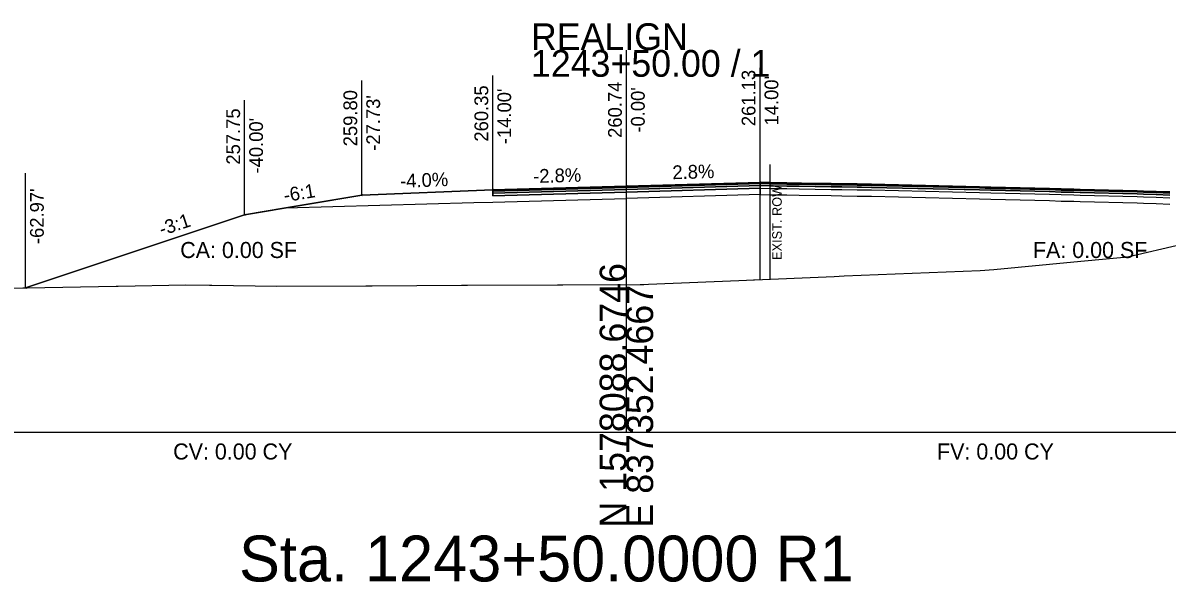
# Model space of a CAD drawing. Extents: x -26 to 6303, y -16 to 9563.
# Drawn here: x 2086.8 to 2206.7, y 4484.3 to 4542.8 of the extents above; entities that cross this region are included whole.
import ezdxf

# ---------------------------------------------------------------- set-up
doc = ezdxf.new("R2010")
doc.units = 0
for name, color, linetype in [('ASPHALT_19MM1', 7, 'Continuous'), ('ASPHALT_9_5MM1', 7, 'Continuous'), ('CONST_DCH', 7, 'Continuous'), ('CONST_LV3', 7, 'Continuous'), ('Default', 7, 'Continuous'), ('Draft_XS_Text', 7, 'Continuous'), ('DTM_P_FINISHED_GRADE', 7, 'Continuous'), ('DTM_P_FINISHED_GRADE2', 7, 'Continuous'), ('DTM_TEMP_DROP', 7, 'Continuous'), ('DTM_X_GROUND', 7, 'Continuous'), ('TRANS_EOP_PAVED', 7, 'Continuous'), ('TRANS_PAVED_SHOULDERS', 7, 'Continuous'), ('XS_CELL', 7, 'Continuous'), ('XS_M_SHAPES_EARTHWORK', 7, 'Continuous'), ('XS_P_ASPHALT', 7, 'Continuous'), ('XS_P_GROUND', 7, 'Continuous'), ('XS_P_SHOULDER', 7, 'Continuous'), ('XS_P_SUBGRADE_GRANULAR', 7, 'Continuous'), ('XS_P_TX_CLEARZONE', 7, 'Continuous'), ('XS_P_TX_FS_BS', 7, 'Continuous'), ('XS_SHEET_EW_TX_AREA', 7, 'Continuous'), ('XS_SHEET_EW_TX_VOLUME', 7, 'Continuous'), ('XS_X_ROW', 7, 'Continuous')]:
    doc.layers.add(name, color=color, linetype=linetype)

msp = doc.modelspace()

# ---------------------------------------------------------------- linework, layer by layer
at = {"layer": 'ASPHALT_19MM1'}
for points in [[(2136, 4525.01), (2136, 4524.74), (2150, 4525.13), (2150, 4525.13), (2164, 4525.53), (2164, 4525.53), (2164, 4525.8), (2164, 4525.8), (2164, 4525.8), (2150, 4525.41), (2150, 4525.41), (2136, 4525.01), (2136, 4525.01)], [(2164, 4525.8), (2164, 4525.53), (2164.98, 4525.51), (2165.2, 4525.51), (2166.82, 4525.49), (2168.12, 4525.47), (2171.44, 4525.41), (2172.57, 4525.4), (2174.17, 4525.37), (2174.62, 4525.36), (2175.69, 4525.35), (2186.99, 4525.08), (2188.17, 4525.03), (2194.33, 4524.91), (2195.56, 4524.86), (2196.9, 4524.83), (2197.54, 4524.8), (2203.52, 4524.66), (2204.19, 4524.63), (2205.52, 4524.6), (2206.93, 4524.53)], [(2206.93, 4524.8), (2205.52, 4524.87), (2204.19, 4524.9), (2203.52, 4524.93), (2197.54, 4525.07), (2196.9, 4525.1), (2195.56, 4525.13), (2194.33, 4525.18), (2188.17, 4525.31), (2186.99, 4525.35), (2175.69, 4525.62), (2174.62, 4525.64), (2174.17, 4525.64), (2172.57, 4525.67), (2171.44, 4525.68), (2168.12, 4525.74), (2166.82, 4525.76), (2165.2, 4525.78), (2164.98, 4525.78), (2164, 4525.8)]]:
    msp.add_lwpolyline(points, dxfattribs=at)
at = {"layer": 'ASPHALT_9_5MM1'}
for points in [[(2136, 4525.35), (2136, 4525.22), (2150, 4525.61), (2150, 4525.61), (2164, 4526.01), (2164, 4526.01), (2164, 4526.13), (2164, 4526.13), (2164, 4526.13), (2150, 4525.74), (2150, 4525.74), (2136, 4525.35), (2136, 4525.35)], [(2164, 4526.13), (2164, 4526.01), (2164.98, 4525.99), (2165.2, 4525.99), (2166.82, 4525.97), (2168.12, 4525.95), (2171.44, 4525.89), (2172.57, 4525.88), (2174.17, 4525.85), (2174.62, 4525.84), (2175.69, 4525.83), (2186.99, 4525.56), (2188.17, 4525.51), (2194.33, 4525.39), (2195.56, 4525.33), (2196.9, 4525.31), (2197.54, 4525.28), (2203.52, 4525.14), (2204.19, 4525.11), (2205.52, 4525.08), (2206.93, 4525.01)], [(2206.93, 4525.14), (2205.52, 4525.2), (2204.19, 4525.23), (2203.52, 4525.26), (2197.54, 4525.4), (2196.9, 4525.43), (2195.56, 4525.46), (2194.33, 4525.51), (2188.17, 4525.64), (2186.99, 4525.69), (2175.69, 4525.95), (2174.62, 4525.97), (2174.17, 4525.98), (2172.57, 4526), (2171.44, 4526.02), (2168.12, 4526.07), (2166.82, 4526.09), (2165.2, 4526.11), (2164.98, 4526.12), (2164, 4526.13)]]:
    msp.add_lwpolyline(points, dxfattribs=at)
at = {"layer": 'CONST_LV3'}
for points in [[(2172.7, 4526), (2164, 4526.13), (2164, 4526.13), (2164, 4526.13), (2150, 4525.74)], [(2164, 4526.13), (2164, 4524.86), (2164.98, 4524.85), (2165.2, 4524.84), (2166.82, 4524.82), (2168.12, 4524.8), (2171.44, 4524.75), (2172.57, 4524.73), (2174.17, 4524.7), (2174.62, 4524.7), (2175.69, 4524.68), (2186.99, 4524.41), (2188.17, 4524.37), (2194.33, 4524.24), (2195.56, 4524.19), (2196.9, 4524.16), (2197.54, 4524.13), (2203.52, 4523.99), (2204.19, 4523.96), (2205.52, 4523.93), (2206.93, 4523.87)], [(2206.93, 4525.14), (2205.52, 4525.2), (2204.19, 4525.23), (2203.52, 4525.26), (2197.54, 4525.4), (2196.9, 4525.43), (2195.56, 4525.46), (2194.33, 4525.51), (2188.17, 4525.64), (2186.99, 4525.69), (2175.69, 4525.95), (2174.62, 4525.97), (2174.17, 4525.97), (2172.57, 4526), (2171.44, 4526.02), (2168.12, 4526.07), (2166.82, 4526.09), (2165.2, 4526.11), (2164.98, 4526.12), (2164, 4526.13)], [(2114.3, 4523.47), (2110, 4522.75)]]:
    msp.add_lwpolyline(points, dxfattribs=at)
at = {"layer": 'Default'}
msp.add_lwpolyline([(2172.7, 4526), (2174.04, 4525.98), (2174.44, 4525.97), (2175.02, 4525.96), (2175.72, 4525.95), (2175.81, 4525.95), (2177.77, 4525.91), (2184.5, 4525.76), (2193.53, 4525.53), (2194.68, 4525.48), (2196.83, 4525.43), (2196.83, 4525.43), (2196.9, 4525.43), (2196.91, 4525.43), (2196.91, 4525.43), (2196.92, 4525.43), (2197.53, 4525.4), (2202.71, 4525.28), (2202.72, 4525.28), (2202.73, 4525.28), (2203.33, 4525.25), (2203.38, 4525.25), (2203.4, 4525.25), (2203.41, 4525.25), (2203.41, 4525.25), (2203.61, 4525.24), (2205.7, 4525.19), (2206.84, 4525.14)], dxfattribs=at)
at = {"layer": 'DTM_P_FINISHED_GRADE'}
msp.add_lwpolyline([(2164, 4526.13), (2164.98, 4526.12), (2165.2, 4526.11), (2166.82, 4526.09), (2168.12, 4526.07), (2171.44, 4526.02), (2172.57, 4526), (2174.17, 4525.97), (2174.62, 4525.97), (2175.69, 4525.95), (2186.99, 4525.69), (2188.17, 4525.64), (2194.33, 4525.51), (2195.56, 4525.46), (2196.9, 4525.43), (2197.54, 4525.4), (2203.52, 4525.26), (2204.19, 4525.23), (2205.52, 4525.2), (2206.93, 4525.14)], dxfattribs=at)
at = {"layer": 'DTM_P_FINISHED_GRADE2'}
msp.add_lwpolyline([(2087.03, 4515.1), (2087.03, 4515.1), (2110, 4522.75), (2122.27, 4524.8), (2136, 4525.35), (2150, 4525.74), (2164, 4526.13), (2164.98, 4526.12), (2165.2, 4526.11), (2166.82, 4526.09), (2168.75, 4526.07), (2172.57, 4526), (2174.17, 4525.98), (2174.62, 4525.97), (2175.69, 4525.95), (2186.99, 4525.69), (2188.17, 4525.64), (2194.33, 4525.51), (2195.56, 4525.46), (2196.9, 4525.43), (2197.54, 4525.4), (2203.52, 4525.26), (2204.19, 4525.23), (2205.52, 4525.2), (2206.93, 4525.14)], dxfattribs=at)
at = {"layer": 'DTM_X_GROUND'}
msp.add_lwpolyline([(2083.56, 4515.05), (2086.77, 4515.1), (2087.21, 4515.09), (2096.52, 4515.27), (2096.76, 4515.26), (2103.82, 4515.4), (2106.31, 4515.39), (2106.46, 4515.38), (2106.55, 4515.37), (2113.37, 4515.28), (2122.69, 4515.32), (2123.36, 4515.32), (2132.73, 4515.37), (2133.35, 4515.37), (2142.78, 4515.41), (2143.34, 4515.41), (2151.46, 4515.45), (2151.81, 4515.45), (2152.31, 4515.48), (2161.78, 4515.86), (2162.58, 4515.91), (2171.76, 4516.28), (2172.82, 4516.34), (2181.74, 4516.71), (2187.06, 4516.92), (2188.51, 4517.01), (2196.9, 4517.81), (2202.49, 4518.34), (2208.21, 4519.66)], dxfattribs=at)
at = {"layer": 'TRANS_PAVED_SHOULDERS'}
for points in [[(2136, 4525.22), (2136, 4525.01), (2150, 4525.41), (2150, 4525.41), (2164, 4525.8), (2164, 4525.8), (2164, 4526.01), (2164, 4526.01), (2164, 4526.01), (2150, 4525.61), (2150, 4525.61), (2136, 4525.22), (2136, 4525.22)], [(2164, 4526.01), (2164, 4525.8), (2164.98, 4525.78), (2165.2, 4525.78), (2166.82, 4525.76), (2168.12, 4525.74), (2171.44, 4525.68), (2172.57, 4525.67), (2174.17, 4525.64), (2174.62, 4525.64), (2175.69, 4525.62), (2186.99, 4525.35), (2188.17, 4525.31), (2194.33, 4525.18), (2195.56, 4525.13), (2196.9, 4525.1), (2197.54, 4525.07), (2203.52, 4524.93), (2204.19, 4524.9), (2205.52, 4524.87), (2206.93, 4524.8)], [(2206.93, 4525.01), (2205.52, 4525.08), (2204.19, 4525.11), (2203.52, 4525.14), (2197.54, 4525.28), (2196.9, 4525.31), (2195.56, 4525.33), (2194.33, 4525.39), (2188.17, 4525.51), (2186.99, 4525.56), (2175.69, 4525.83), (2174.62, 4525.84), (2174.17, 4525.85), (2172.57, 4525.88), (2171.44, 4525.89), (2168.12, 4525.95), (2166.82, 4525.97), (2165.2, 4525.99), (2164.98, 4525.99), (2164, 4526.01)]]:
    msp.add_lwpolyline(points, dxfattribs=at)
at = {"layer": 'XS_CELL'}
for p, q in [((2150, 4500), (2150, 4540)), ((2000, 4500), (2150, 4500)), ((2150, 4500), (2300, 4500))]:
    msp.add_line(p, q, dxfattribs=at)
at = {"layer": 'XS_M_SHAPES_EARTHWORK'}
msp.add_lwpolyline([(2087.03, 4515.1), (2087.21, 4515.09), (2096.52, 4515.27), (2096.76, 4515.26), (2103.82, 4515.4), (2106.31, 4515.39), (2106.46, 4515.38), (2106.55, 4515.37), (2113.37, 4515.28), (2122.69, 4515.32), (2123.36, 4515.32), (2132.73, 4515.37), (2133.35, 4515.37), (2142.78, 4515.41), (2143.34, 4515.41), (2151.46, 4515.45), (2151.81, 4515.45), (2152.31, 4515.48), (2161.78, 4515.86), (2162.58, 4515.91), (2164, 4515.96), (2164, 4525.53), (2150, 4525.13), (2136, 4524.74), (2136, 4525.01), (2136, 4525.22), (2136, 4525.35), (2122.27, 4524.8), (2114.3, 4523.47), (2110, 4522.75)], close=True, dxfattribs=at)
at = {"layer": 'XS_P_ASPHALT'}
msp.add_lwpolyline([(2164, 4526.13), (2164.98, 4526.12), (2165.2, 4526.11), (2166.82, 4526.09), (2168.12, 4526.07), (2171.44, 4526.02), (2172.57, 4526), (2174.17, 4525.97), (2174.62, 4525.97), (2175.69, 4525.95), (2186.99, 4525.69), (2188.17, 4525.64), (2194.33, 4525.51), (2195.56, 4525.46), (2196.9, 4525.43), (2197.54, 4525.4), (2203.52, 4525.26), (2204.19, 4525.23), (2205.52, 4525.2), (2206.93, 4525.14)], dxfattribs=at)
at = {"layer": 'XS_P_GROUND'}
msp.add_lwpolyline([(2122.27, 4524.8), (2110, 4522.75), (2087.03, 4515.1)], dxfattribs=at)
at = {"layer": 'XS_P_SHOULDER'}
msp.add_lwpolyline([(2122.27, 4524.8), (2122.27, 4524.8), (2136, 4525.35)], dxfattribs=at)
at = {"layer": 'XS_P_SUBGRADE_GRANULAR'}
for points in [[(2114.3, 4523.47), (2114.3, 4523.47), (2134, 4524.02), (2136, 4524.08), (2136, 4524.08)], [(2136, 4524.08), (2150, 4524.47), (2150, 4524.47)], [(2164, 4524.86), (2164, 4524.86), (2150, 4524.47)], [(2164, 4524.86), (2164.98, 4524.85), (2165.2, 4524.84), (2166.82, 4524.82), (2168.12, 4524.8), (2171.44, 4524.75), (2172.57, 4524.73), (2174.17, 4524.7), (2174.62, 4524.7), (2175.69, 4524.68), (2186.99, 4524.41), (2188.17, 4524.37), (2194.33, 4524.24), (2195.56, 4524.19), (2196.9, 4524.16), (2197.54, 4524.13), (2203.52, 4523.99), (2204.19, 4523.96), (2205.52, 4523.93), (2206.93, 4523.87)]]:
    msp.add_lwpolyline(points, dxfattribs=at)
at = {"layer": 'XS_P_TX_CLEARZONE'}
for p, q in [((2164, 4526.13), (2164, 4538.13)), ((2136, 4525.35), (2136, 4537.35)), ((2150, 4525.74), (2150, 4537.74)), ((2122.27, 4524.8), (2122.27, 4536.8)), ((2110, 4522.75), (2110, 4534.75)), ((2087.03, 4515.1), (2087.03, 4527.1))]:
    msp.add_line(p, q, dxfattribs=at)
at = {"layer": 'XS_X_ROW'}
msp.add_line((2165.08, 4516.01), (2165.08, 4528.01), dxfattribs=at)

# ---------------------------------------------------------------- texts
at = {"layer": 'CONST_DCH'}
for p in [(2163.92, 4526.01), (2135.92, 4525.23), (2149.92, 4525.62)]:
    msp.add_text('X', height=0.24, dxfattribs=at).set_placement(p)
at = {"layer": 'CONST_LV3'}
msp.add_text('X', height=0.24, dxfattribs=at).set_placement((2109.92, 4522.63))
at = {"layer": 'Draft_XS_Text'}
msp.add_text('Sta. 1243+50.0000 R1', height=4.8, dxfattribs=at).set_placement((2109.41, 4484.35))
at = {"layer": 'DTM_TEMP_DROP'}
msp.add_text('X', height=0.24, dxfattribs=at).set_placement((2086.95, 4514.98))
at = {"layer": 'TRANS_EOP_PAVED'}
msp.add_text('X', height=0.24, dxfattribs=at).set_placement((2086.95, 4514.98))
at = {"layer": 'XS_CELL'}
for s, p in [('REALIGN', (2140, 4540)), ('1243+50.00 / 1', (2140, 4537.2))]:
    msp.add_text(s, height=2.8, dxfattribs=at).set_placement(p)
for s, p in [('N 1578088.6746', (2150, 4490)), ('E 837352.4667', (2152.8, 4490))]:
    msp.add_text(s, height=2.8, rotation=90, dxfattribs=at).set_placement(p)
at = {"layer": 'XS_P_SUBGRADE_GRANULAR'}
msp.add_text('X', height=0.24, dxfattribs=at).set_placement((2122.19, 4524.68))
at = {"layer": 'XS_P_TX_CLEARZONE'}
for s, p in [('261.13', (2163.52, 4532.03)), ("14.00'", (2165.92, 4532.1)), ('259.80', (2121.79, 4529.92)), ('260.35', (2135.52, 4530.41)), ("-14.00'", (2137.92, 4530.14)), ('260.74', (2149.52, 4530.8)), ("-0.00'", (2151.92, 4531.35)), ("-27.73'", (2124.19, 4529.45)), ('257.75', (2109.52, 4528)), ("-40.00'", (2111.92, 4527.07)), ("-62.97'", (2088.95, 4519.68))]:
    msp.add_text(s, height=1.44, rotation=90, dxfattribs=at).set_placement(p)
at = {"layer": 'XS_P_TX_FS_BS'}
for s, rotation, p in [('-2.8%', 1.6039, (2140.25, 4526.07)), ('2.8%', 1.6039, (2154.84, 4526.47)), ('-4.0%', 2.2906, (2126.32, 4525.56)), ('-6:1', 9.4642, (2114.21, 4524.06)), ('-3:1', 18.4332, (2101.31, 4520.52))]:
    msp.add_text(s, height=1.44, rotation=rotation, dxfattribs=at).set_placement(p)
at = {"layer": 'XS_SHEET_EW_TX_AREA'}
for s, p in [('CA: 0.00 SF', (2103.25, 4518.22)), ('FA: 0.00 SF', (2192.6, 4518.22))]:
    msp.add_text(s, height=1.68, dxfattribs=at).set_placement(p)
at = {"layer": 'XS_SHEET_EW_TX_VOLUME'}
for s, p in [('CV: 0.00 CY', (2102.51, 4497.12)), ('FV: 0.00 CY', (2182.55, 4497.12))]:
    msp.add_text(s, height=1.68, dxfattribs=at).set_placement(p)
at = {"layer": 'XS_X_ROW'}
msp.add_text('EXIST. ROW', height=1, rotation=90, dxfattribs=at).set_placement((2166.28, 4518.01))

doc.saveas('drawing.dxf')
